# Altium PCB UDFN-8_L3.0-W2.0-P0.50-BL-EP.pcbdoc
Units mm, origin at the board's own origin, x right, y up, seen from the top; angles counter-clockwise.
Board outline 14.91 x 16.26 mm, 2 copper layers (Top Layer, Bottom Layer), stack 0.07 mm thick; 1 components, 0 nets, 9 pads, 0 vias.
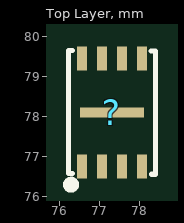
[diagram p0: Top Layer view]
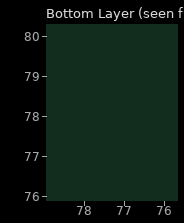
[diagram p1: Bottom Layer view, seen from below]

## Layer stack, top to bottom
Top Solder Mask Layer: solder mask 0.01, Dk 3.3
Top Layer: signal copper 0.035
Bottom Layer: signal copper 0.035
Bottom Solder Mask Layer: solder mask 0.01, Dk 3.3

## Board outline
84.76,69.85 69.85,69.85 69.85,86.111 84.76,86.111

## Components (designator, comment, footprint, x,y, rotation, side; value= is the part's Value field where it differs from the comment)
? "UDFN-8_L3.0-W2.0-P0.50-BL-EP" UDFN-8_L3.0-W2.0-P0.50-BL-EP 77.32,78.11 r0 top

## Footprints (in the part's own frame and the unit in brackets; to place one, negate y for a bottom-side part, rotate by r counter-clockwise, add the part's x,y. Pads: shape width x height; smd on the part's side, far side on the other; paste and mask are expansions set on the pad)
UDFN-8_L3.0-W2.0-P0.50-BL-EP [mm]
  rect 0.25x0.6 smd paste+0 mask+0.051: 1(-0.75,-1.349) 2(-0.252,-1.351) 3(0.248,-1.351) 4(0.748,-1.351) 5(0.75,1.351) 6(0.25,1.351) 7(-0.25,1.351) 8(-0.75,1.351)
  rect 1.6x0.25 smd paste+0 mask+0.051: 9(0,0.001)
  silkscreen extent -1.12,-1.91 1.09,1.55

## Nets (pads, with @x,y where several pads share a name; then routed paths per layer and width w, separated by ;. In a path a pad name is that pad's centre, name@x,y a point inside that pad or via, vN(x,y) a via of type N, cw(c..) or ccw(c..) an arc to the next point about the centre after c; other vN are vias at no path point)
pads on no net: ?.1 ?.2 ?.3 ?.4 ?.5 ?.6 ?.7 ?.8 ?.9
